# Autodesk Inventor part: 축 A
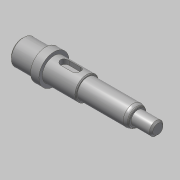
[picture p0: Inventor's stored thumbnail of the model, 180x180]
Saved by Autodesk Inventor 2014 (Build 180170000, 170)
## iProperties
Created: 2020-04
Part Number: 축 A
Material: 강철, 연강
Document SubType Name: Modeling
Designer: mduedu
Density: 7.86 g/cm^3
Appearance: 강철
Mass: 83.1595 g
Surface Area: 37.6208 cm^2
Volume: 10.5801 cm^3
Author: mduedu
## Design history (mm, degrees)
sketch "스케치1"
  geometry: L1 (0, 0)-(14, 0); L2 (14, 0)-(14, 7.5); L3 (14, 7.5)-(0, 7.5); L4 (0, 7.5)-(0, 0); L5 (14, 0)-(19, 0); L6 (19, 0)-(19, 9); L7 (19, 9)-(14, 9); L8 (14, 9)-(14, 0); L9 (19, 0)-(39, 0); L10 (39, 0)-(39, 7); L11 (39, 7)-(19, 7); L12 (19, 7)-(19, 0); L13 (39, 0)-(69, 0); L14 (69, 0)-(69, 6); L15 (69, 6)-(39, 6); L16 (39, 6)-(39, 0); L17 (69, 0)-(81, 0); L18 (81, 0)-(81, 4); L19 (81, 4)-(69, 4); L20 (69, 4)-(69, 0)
  constraints: 40 end point, 10 parallel, 5 horizontal, 5 perpendicular
  dimensions: "d0" = 81 distance between parallel lines of L18 L4; "d2" = 14 distance of L2.end L3.end; "d3" = 5 distance of L6.end L7.end; "d4" = 12 distance of L18.end L19.end; "d5" = 8 diameter of L19 L17; "d6" = 12 diameter of L15 L13; "d7" = 14 diameter of L11 L9; "d8" = 15 diameter of L3 L1; "d9" = 18 diameter of L7 L5; "d10" = 42 distance between parallel lines of L10 L18
revolve "회전1" sketch "스케치1" stored, may be unused: angle "d11" = 90 deg
sketch "스케치2"
  geometry: L1 (0, -7.5)-(0, 7.5) reference; L2 (0, 7.5)-(14, 7.5) reference; L3 (14, 7.5)-(14, 9) reference; L4 (14, 9)-(19, 9) reference; L5 (19, 9)-(19, 7) reference; L6 (19, 7)-(39, 7) reference; L7 (39, 7)-(39, 6) reference; L8 (39, 6)-(69, 6) reference; L9 (69, 6)-(69, 4) reference; L10 (69, 4)-(81, 4) reference; L11 (81, 4)-(81, -4) reference; L12 (81, -4)-(69, -4) reference; L13 (69, -4)-(69, -6) reference; L14 (69, -6)-(39, -6) reference; L15 (39, -6)-(39, -7) reference; L16 (39, -7)-(19, -7) reference; L17 (19, -7)-(19, -9) reference; L18 (19, -9)-(14, -9) reference; L19 (14, -9)-(14, -7.5) reference; L20 (14, -7.5)-(0, -7.5) reference; L21 (81, -4)-(73, -4); L22 (73, -4)-(73, -2.8); L23 (73, -2.8)-(81, -2.8); L24 (81, -2.8)-(81, -4); 1 further point
  constraints: 8 end point, 2 parallel, 1 horizontal, 1 perpendicular
  dimensions: "d12" = 8 distance of L22.end L23.end; "d13" = 1.2 distance of L21.end L22.end
extrude "돌출1" cut sketch "스케치2" stored distance "d14" = 2; taper "d15" = 0 deg
fillet "모깎기1" dims "d16" = 1
sketch "스케치3"
  geometry: L1 (0, -7.5)-(0, 7.5) reference; L2 (0, 7.5)-(14, 7.5) reference; L3 (14, 7.5)-(14, 9) reference; L4 (14, 9)-(19, 9) reference; L5 (19, 9)-(19, 7) reference; L6 (19, 7)-(39, 7) reference; L7 (39, 7)-(39, 6) reference; L8 (39, 6)-(69, 6) reference; L9 (69, 6)-(69, 4) reference; L10 (69, 4)-(81, 4) reference; L11 (81, 4)-(81, -2.8) reference; L12 (81, -2.8)-(73, -2.8) reference; L13 (73, -2.8)-(73, -4) reference; L14 (73, -4)-(69, -4) reference; L15 (69, -4)-(69, -6) reference; L16 (69, -6)-(39, -6) reference; L17 (39, -6)-(39, -7) reference; L18 (39, -7)-(19, -7) reference; L19 (19, -7)-(19, -9) reference; L20 (19, -9)-(14, -9) reference; L21 (14, -9)-(14, -7.5) reference; L22 (14, -7.5)-(0, -7.5) reference; L23 (23, 7)-(35, 7); L24 (35, 7)-(35, 4); L25 (35, 4)-(23, 4); L26 (23, 4)-(23, 7); 1 further point
  constraints: 8 end point, 2 parallel, 1 horizontal, 1 perpendicular, 1 point on line
  dimensions: "d17" = 12 distance of L24.end L25.end; "d18" = 3 distance of L23.end L24.end; "d19" = 4 distance from line of L26 L4.end
extrude "돌출2" cut sketch "스케치3" stored distance "d20" = 5; taper "d21" = 0 deg
fillet "모깎기2" dims "d22" = 2.5
chamfer "모따기1" distance "d23" = 1; stored, may be unused: second distance "d24" = 2, angle "d25" = 45 deg
chamfer "모따기2" distance "d26" = 0.5; stored, may be unused: second distance "d27" = 2, angle "d28" = 45 deg
fillet "모깎기3" dims "d29" = 0.3
chamfer "모따기3" distance "d30" = 1.56; stored, may be unused: second distance "d31" = 2, angle "d32" = 30 deg
fillet "모깎기4" dims "d33" = 4, "d34" = 0.5
node "솔리드1"
node "절단 모서리 투영1"
node "절단 모서리 투영2"
